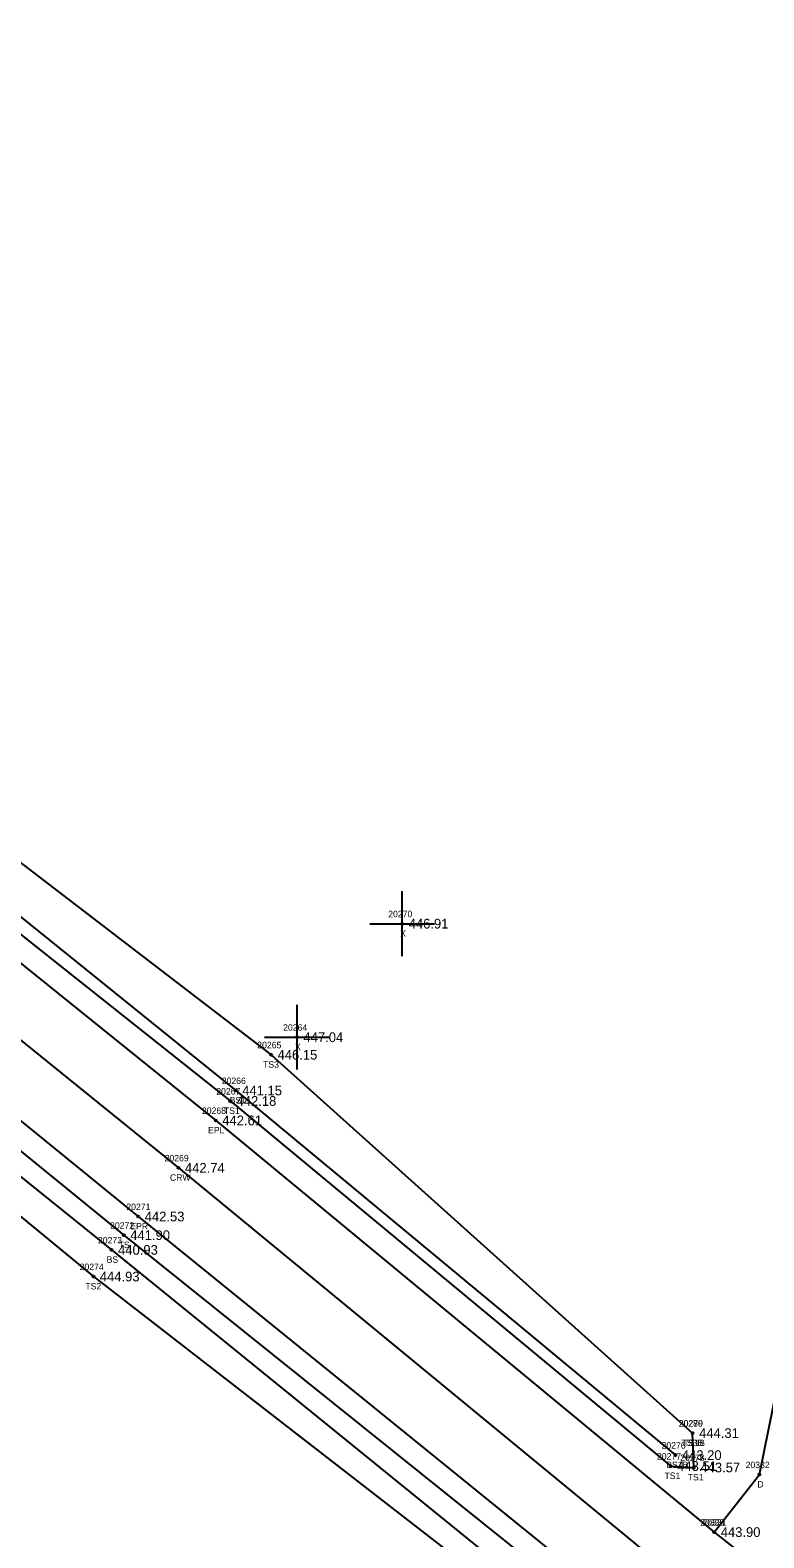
# Model space of a CAD drawing. Extents: x 1613836 to 1615109, y 777151 to 778248.
# Drawn here: x 1614809.5 to 1614922.8, y 777339.3 to 777572.2 of the extents above; entities that cross this region are included whole.
import ezdxf

# ---------------------------------------------------------------- set-up
doc = ezdxf.new("R2010")
doc.units = 0
for name, color, linetype in [('RD_DTM_BkLn1', 7, 'Continuous'), ('RD_DTM_BkLn2', 7, 'Continuous'), ('RD_DTM_BkLn_txCode', 7, 'Continuous'), ('RD_EX_Driveway', 7, 'Continuous'), ('RD_EX_Driveway_txCode', 7, 'Continuous'), ('RD_EX_Misc', 7, 'Continuous'), ('RD_EX_Misc_txCode', 7, 'Continuous'), ('RD_EX_Road', 7, 'Continuous'), ('RD_EX_Road_txCode', 7, 'Continuous'), ('RD_EX_TX_Driveway_ELEV', 7, 'Continuous'), ('RD_EX_TX_Misc_ELEV', 7, 'Continuous'), ('RD_EX_TX_Road_ELEV', 7, 'Continuous'), ('RD_HC_Survey_ELEV', 7, 'Continuous'), ('RD_HC_Survey_txCode', 7, 'Continuous'), ('RD_SMD_Locator', 7, 'Continuous')]:
    doc.layers.add(name, color=color, linetype=linetype)

msp = doc.modelspace()

# ---------------------------------------------------------------- linework, layer by layer
at = {"layer": 'RD_DTM_BkLn1'}
msp.add_lwpolyline([(1614479.01, 777681.63), (1614521.59, 777647.42), (1614599.56, 777584.67), (1614677.14, 777521.99), (1614754.7, 777459.32), (1614832.45, 777396.45), (1614909.52, 777332.99), (1614951.1, 777299.39), (1614987.2, 777270.31), (1615065.15, 777207.54)], dxfattribs=at)
at = {"layer": 'RD_DTM_BkLn2'}
for points in [[(1614480.98, 777699.79), (1614497.59, 777703), (1614522.19, 777696.07), (1614543.87, 777680.98), (1614547.65, 777678.09), (1614587.23, 777635.96), (1614610.74, 777599.44), (1614633.11, 777578.17), (1614686.46, 777534.25), (1614763.32, 777471.34), (1614841.29, 777408.4), (1614909.19, 777352.07)], [(1614487.8, 777694.98), (1614468.11, 777671.48), (1614470.95, 777667.94), (1614510.68, 777634.64), (1614563.11, 777597.11), (1614590.8, 777573.1), (1614668.37, 777511.43), (1614746.83, 777448.93), (1614824, 777386.05), (1614902.11, 777323.38), (1614943.6, 777288.77), (1614978.33, 777258.85), (1615057.35, 777197.32)], [(1614487.8, 777694.98), (1614492.09, 777693.24), (1614539.12, 777670.15), (1614581.25, 777629.02), (1614608.07, 777595.47), (1614631.79, 777576.16), (1614684.94, 777532.19), (1614761.79, 777469.29), (1614840.42, 777406.78), (1614908.46, 777350.38), (1614912.05, 777350.16), (1614911.85, 777355.47)], [(1614459.93, 777668.19), (1614463.78, 777659.09), (1614488.02, 777636.81), (1614504.08, 777625.83), (1614559.77, 777590.67), (1614588.99, 777571.17), (1614666.25, 777508.81), (1614744.8, 777446.03), (1614822.12, 777383.78), (1614899.86, 777320.65), (1614938.98, 777288.55), (1614940.53, 777287.22)], [(1614614.42, 777605.82), (1614635.25, 777582.12), (1614690.07, 777537.42), (1614767.2, 777474.86), (1614846.75, 777413.92), (1614911.85, 777355.47)], [(1614586.97, 777568.57), (1614664.83, 777506.94), (1614742.31, 777443.08), (1614819.3, 777379.66), (1614897.91, 777318.71), (1614936.23, 777288.24)]]:
    msp.add_lwpolyline(points, dxfattribs=at)
at = {"layer": 'RD_EX_Driveway'}
msp.add_lwpolyline([(1614915.19, 777340.18), (1614922.15, 777349.06), (1614929.13, 777383.31)], dxfattribs=at)
at = {"layer": 'RD_EX_Misc'}
for p, q in [((1614867, 777429.17), (1614867, 777439.17)), ((1614862, 777434.17), (1614872, 777434.17)), ((1614850.75, 777411.63), (1614850.75, 777421.63)), ((1614845.75, 777416.63), (1614855.75, 777416.63))]:
    msp.add_line(p, q, dxfattribs=at)
at = {"layer": 'RD_EX_Road'}
for points in [[(1614484.15, 777687.93), (1614479.01, 777681.63), (1614474.14, 777675.5), (1614516.4, 777641.23), (1614565.54, 777600.82), (1614593.96, 777577.93), (1614671.57, 777514.59), (1614748.82, 777451.94), (1614826.23, 777388.93), (1614903.92, 777325.97), (1614945.38, 777292), (1614981.73, 777262.81), (1615059.73, 777200.12)], [(1614484.15, 777687.93), (1614527.25, 777653.67), (1614604.97, 777591.41), (1614629.13, 777572.93), (1614683.14, 777529.85), (1614759.91, 777466.85), (1614838.21, 777403.78), (1614915.19, 777340.18), (1614934.98, 777324.5), (1615070.79, 777214.66)]]:
    msp.add_lwpolyline(points, dxfattribs=at)
at = {"layer": 'RD_SMD_Locator'}
for centre in [(1614867, 777434.17), (1614850.75, 777416.63), (1614846.75, 777413.92), (1614841.29, 777408.4), (1614840.42, 777406.78), (1614838.21, 777403.78), (1614832.45, 777396.45), (1614826.23, 777388.93), (1614824, 777386.05), (1614822.12, 777383.78), (1614819.3, 777379.66), (1614911.85, 777355.47), (1614911.85, 777355.47), (1614909.19, 777352.07), (1614908.46, 777350.38), (1614912.05, 777350.16), (1614922.15, 777349.06), (1614915.19, 777340.18), (1614915.19, 777340.18)]:
    msp.add_circle(centre, 0.15, dxfattribs=at)

# ---------------------------------------------------------------- texts
at = {"layer": 'RD_DTM_BkLn_txCode'}
for s, p in [('20265', (1614844.61, 777414.92)), ('TS3', (1614845.51, 777411.92)), ('20266', (1614839.13, 777409.4)), ('20267', (1614838.28, 777407.78)), ('TS1', (1614839.46, 777404.78)), ('BS1', (1614840.35, 777406.4)), ('20272', (1614821.88, 777387.05)), ('20273', (1614820.01, 777384.78)), ('TS', (1614823.2, 777384.05)), ('BS', (1614821.35, 777381.78)), ('20274', (1614817.18, 777380.66)), ('TS2', (1614818.06, 777377.66)), ('20280', (1614909.69, 777356.47)), ('20279', (1614909.73, 777356.47)), ('TS3B', (1614910.13, 777353.47)), ('TS1B', (1614910.41, 777353.47)), ('20277', (1614906.34, 777351.38)), ('20276', (1614907.05, 777353.07)), ('20278', (1614909.94, 777351.16)), ('BS1B', (1614907.77, 777350.07)), ('TS1', (1614907.5, 777348.38)), ('TS1', (1614911.09, 777348.16))]:
    msp.add_text(s, height=1, dxfattribs=at).set_placement(p)
at = {"layer": 'RD_EX_Driveway_txCode'}
for s, p in [('20332', (1614920.03, 777350.06)), ('D', (1614921.84, 777347.06)), ('20331', (1614913.35, 777341.18))]:
    msp.add_text(s, height=1, dxfattribs=at).set_placement(p)
at = {"layer": 'RD_EX_Misc_txCode'}
for s, p in [('20270', (1614864.84, 777435.17)), ('X', (1614866.68, 777432.17)), ('20264', (1614848.61, 777417.63)), ('X', (1614850.44, 777414.63))]:
    msp.add_text(s, height=1, dxfattribs=at).set_placement(p)
at = {"layer": 'RD_EX_Road_txCode'}
for s, p in [('20268', (1614836.07, 777404.78)), ('EPL', (1614837.01, 777401.78)), ('20271', (1614824.39, 777389.93)), ('EPR', (1614825, 777386.93)), ('20330', (1614913.03, 777341.18))]:
    msp.add_text(s, height=1, dxfattribs=at).set_placement(p)
at = {"layer": 'RD_EX_TX_Driveway_ELEV'}
msp.add_text('443.90', height=1.5, dxfattribs=at).set_placement((1614916.19, 777339.43))
at = {"layer": 'RD_EX_TX_Misc_ELEV'}
for s, p in [('446.91', (1614868, 777433.42)), ('447.04', (1614851.75, 777415.88)), ('446.15', (1614847.75, 777413.17)), ('441.15', (1614842.29, 777407.65)), ('442.18', (1614841.42, 777406.03)), ('441.90', (1614825, 777385.3)), ('440.93', (1614823.12, 777383.03)), ('444.93', (1614820.3, 777378.91)), ('444.31', (1614912.85, 777354.72)), ('444.31', (1614912.85, 777354.72)), ('443.20', (1614910.19, 777351.32)), ('443.51', (1614909.46, 777349.63)), ('443.57', (1614913.05, 777349.41))]:
    msp.add_text(s, height=1.5, dxfattribs=at).set_placement(p)
at = {"layer": 'RD_EX_TX_Road_ELEV'}
for s, p in [('442.61', (1614839.21, 777403.03)), ('442.53', (1614827.23, 777388.18)), ('443.90', (1614916.19, 777339.43))]:
    msp.add_text(s, height=1.5, dxfattribs=at).set_placement(p)
at = {"layer": 'RD_HC_Survey_ELEV'}
msp.add_text('442.74', height=1.5, dxfattribs=at).set_placement((1614833.45, 777395.7))
at = {"layer": 'RD_HC_Survey_txCode'}
for s, p in [('20269', (1614830.3, 777397.45)), ('CRW', (1614831.13, 777394.45))]:
    msp.add_text(s, height=1, dxfattribs=at).set_placement(p)

doc.saveas('drawing.dxf')
